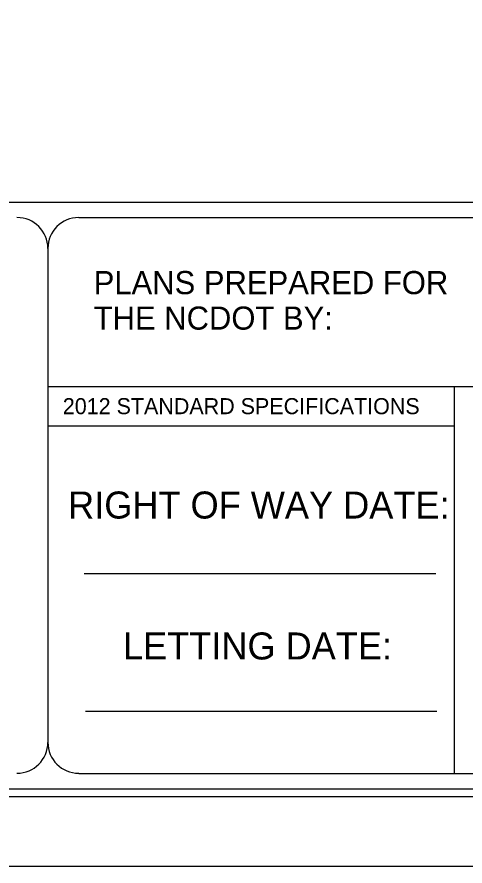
# Model space of a CAD drawing. Extents: x 2431000 to 2534000, y 645879 to 714000.
# Drawn here: x 2464804.7 to 2464949.7, y 678900 to 679175 of the extents above; entities that cross this region are included whole.
import ezdxf

# ---------------------------------------------------------------- set-up
doc = ezdxf.new("R2010")
doc.units = 0
for name, color, linetype in [('Sheet Plot Border Inside CELL', 7, 'Continuous'), ('Sheet Plot Border Outside CELL', 7, 'Continuous'), ('Sheet Title CELL', 7, 'Continuous')]:
    doc.layers.add(name, color=color, linetype=linetype)

msp = doc.modelspace()

# ---------------------------------------------------------------- linework, layer by layer
at = {"layer": 'Sheet Plot Border Inside CELL'}
msp.add_lwpolyline([(2463866.2, 678922.5), (2465532.2, 678922.5), (2465532.2, 679977.5), (2463866.2, 679977.5)], close=True, dxfattribs=at)
at = {"layer": 'Sheet Plot Border Outside CELL'}
msp.add_lwpolyline([(2463853.2, 678900), (2465536.7, 678900), (2465536.7, 680000), (2463853.2, 680000)], close=True, dxfattribs=at)
at = {"layer": 'Sheet Title CELL'}
for p, q in [((2464084.7, 679115), (2465504.7, 679115)), ((2464824.7, 679110), (2465109.7, 679110)), ((2464814.7, 679100), (2464814.7, 678940)), ((2465119.7, 679055.24), (2464814.7, 679055.25)), ((2464946.25, 679055.25), (2464946.25, 678930)), ((2464946.25, 679042.49), (2464814.7, 679042.5)), ((2464908.35, 679042.5), (2464908.35, 679042.5)), ((2464940.25, 678994.65), (2464826.5, 678994.65)), ((2464883.35, 678994.64), (2464883.35, 678994.64)), ((2464940.65, 678950.05), (2464826.9, 678950.05))]:
    msp.add_line(p, q, dxfattribs=at)
for points in [[(2464824.7, 678930), (2465109.7, 678929.99)], [(2464029.7, 678924.99), (2465509.7, 678924.99)]]:
    msp.add_lwpolyline(points, dxfattribs=at)
for centre, start, end in [((2464804.7, 679100.04), 0, 90), ((2464824.7, 679100.04), 90, 180), ((2464804.7, 678940.04), 270, 0), ((2464824.7, 678940.04), 180, 270)]:
    msp.add_arc(centre, 10, start, end, dxfattribs=at)

# ---------------------------------------------------------------- texts
for s, height, p in [('PLANS PREPARED FOR ', 7.4994, (2464829.53, 679085.22)), ('THE NCDOT BY:', 7.4994, (2464829.53, 679073.72)), ('2012 STANDARD SPECIFICATIONS', 5.2, (2464819.54, 679046.35)), ('RIGHT OF WAY DATE: ', 8.7498, (2464821.25, 679012.55)), ('LETTING DATE:', 8.7498, (2464839.01, 678966.9))]:
    msp.add_text(s, height=height, dxfattribs=at).set_placement(p)

doc.saveas('drawing.dxf')
